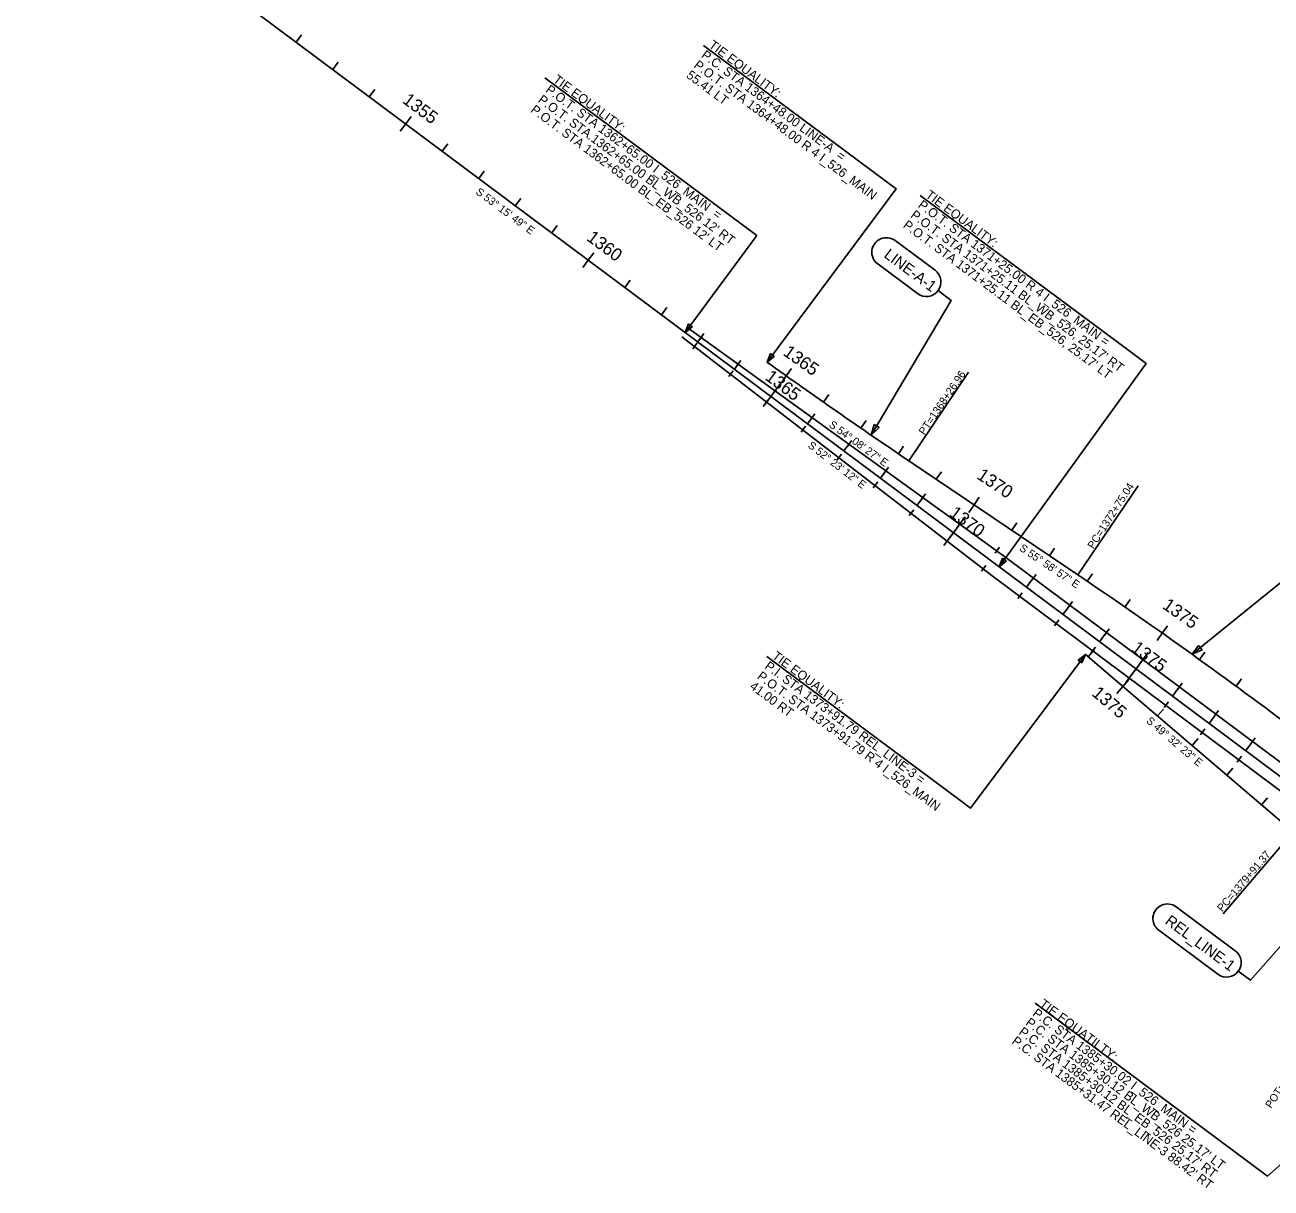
# Model space of a CAD drawing. Extents: x 2339300 to 2355400, y 360879 to 381052.
# Drawn here: x 2342035 to 2344770, y 370020 to 372573 of the extents above; entities that cross this region are included whole.
import ezdxf

# ---------------------------------------------------------------- set-up
doc = ezdxf.new("R2010")
doc.units = 0
for name, color, linetype in [('RD_HC_Cl', 7, 'Continuous'), ('RD_HC_CL_Rel', 7, 'Continuous'), ('RD_HC_Data', 7, 'Continuous'), ('RD_HC_Data_Rel', 7, 'Continuous'), ('RD_HC_Data_Tic', 7, 'Continuous'), ('RD_HC_Data_Tic_Rel', 7, 'Continuous'), ('RD_HC_TX_Rel_Sta50', 7, 'Continuous'), ('RD_HC_TX_Sta50', 7, 'Continuous'), ('RD_PD_Final_TX', 7, 'Continuous')]:
    doc.layers.add(name, color=color, linetype=linetype)

msp = doc.modelspace()

# ---------------------------------------------------------------- linework, layer by layer
at = {"layer": 'RD_HC_Cl'}
for p, q in [((2339299.7, 375020.3), (2345298.7, 370542.8)), ((2343974.3, 371616), (2344345.7, 371365.3))]:
    msp.add_line(p, q, dxfattribs=at)
for centre, radius, start, end in [((2351247.1, 382391.3), 13000, 234.31228, 235.98251), ((2338191.8, 362247.8), 11000, 52.99132, 55.9825)]:
    msp.add_arc(centre, radius, start, end, dxfattribs=at)
at = {"layer": 'RD_HC_CL_Rel'}
for p, q in [((2343490.7, 371907.2), (2344187.8, 371403.4)), ((2343476.4, 371888), (2344157.7, 371363.1)), ((2344187.8, 371403.4), (2345313.8, 370563)), ((2344157.7, 371363.1), (2345283.7, 370522.7)), ((2344362.1, 371190.8), (2344818.2, 370801.7))]:
    msp.add_line(p, q, dxfattribs=at)
at = {"layer": 'RD_HC_Data'}
for p, q in [((2344032.2, 372034), (2343944.5, 372099.3)), ((2343906.3, 372048), (2343994, 371982.7)), ((2343974.3, 371616), (2344105.5, 371810.3)), ((2344345.7, 371365.3), (2344477.9, 371561.2)), ((2344691.2, 370540.3), (2344561.4, 370636.8)), ((2344523.2, 370585.5), (2344653, 370488.9))]:
    msp.add_line(p, q, dxfattribs=at)
for points in [[(2344038.8, 371989.3), (2344067.9, 371967.6), (2343892, 371672.1)], [(2344888.7, 371354.8), (2344841.5, 371389.9), (2344596.3, 371191.1)], [(2344697.8, 370495.5), (2344724.3, 370475.8), (2344930.9, 370709.1)]]:
    msp.add_lwpolyline(points, dxfattribs=at)
for points in [[(2343898.5, 371695.2), (2343892, 371672.1), (2343909.2, 371688.8)], [(2344610.4, 371210.5), (2344596.3, 371191.1), (2344618.2, 371200.9)]]:
    msp.add_lwpolyline(points, close=True, dxfattribs=at)
for centre, start, end in [((2343925.4, 372073.6), 53.3467, 233.3467), ((2344013.1, 372008.4), 233.3467, 53.3467), ((2344542.3, 370611.1), 53.3467, 233.3467), ((2344672.1, 370514.6), 233.3467, 53.3467)]:
    msp.add_arc(centre, 32, start, end, dxfattribs=at)
at = {"layer": 'RD_HC_Data_Rel'}
msp.add_line((2344664.4, 370621.3), (2344818.2, 370801.7), dxfattribs=at)
at = {"layer": 'RD_HC_Data_Tic'}
for p, q in [((2342630.1, 372534.6), (2342642, 372550.7)), ((2342710.2, 372474.8), (2342722.2, 372490.9)), ((2342790.4, 372415), (2342802.3, 372431)), ((2342870.5, 372355.2), (2342882.5, 372371.2)), ((2342870.5, 372355.2), (2342858.5, 372339.2)), ((2342950.6, 372295.4), (2342962.6, 372311.4)), ((2343030.8, 372235.6), (2343042.7, 372251.6)), ((2343110.9, 372175.8), (2343122.9, 372191.8)), ((2343191.1, 372115.9), (2343203, 372132)), ((2343271.2, 372056.1), (2343283.2, 372072.2)), ((2343271.2, 372056.1), (2343259.2, 372040.1)), ((2343351.3, 371996.3), (2343363.3, 372012.3)), ((2343431.5, 371936.5), (2343443.4, 371952.5)), ((2343511.6, 371876.7), (2343523.6, 371892.7)), ((2343591.8, 371816.9), (2343603.7, 371832.9)), ((2343705.7, 371802.3), (2343694.1, 371786)), ((2343705.7, 371802.3), (2343717.3, 371818.6)), ((2343671.9, 371757.1), (2343683.9, 371773.1)), ((2343671.9, 371757.1), (2343659.9, 371741)), ((2343787.3, 371744.6), (2343798.8, 371761)), ((2343752, 371697.3), (2343764, 371713.3)), ((2343869.5, 371687.6), (2343880.8, 371704)), ((2343832.2, 371637.4), (2343844.1, 371653.5)), ((2343952, 371631.1), (2343963.2, 371647.7)), ((2343912.3, 371577.6), (2343924.3, 371593.7)), ((2344034.9, 371575.2), (2344046.1, 371591.7)), ((2343992.5, 371517.8), (2344004.4, 371533.8)), ((2344117.8, 371519.2), (2344129, 371535.8)), ((2344117.8, 371519.2), (2344106.6, 371502.6)), ((2344072.6, 371458), (2344084.6, 371474)), ((2344200.7, 371463.3), (2344211.8, 371479.8)), ((2344072.6, 371458), (2344060.6, 371442)), ((2344283.5, 371407.3), (2344294.7, 371423.9)), ((2344366.4, 371351.4), (2344377.6, 371367.9)), ((2344232.9, 371338.4), (2344244.8, 371354.4)), ((2344448.9, 371294.8), (2344460.3, 371311.3)), ((2344313, 371278.6), (2344325, 371294.6)), ((2344530.9, 371237.6), (2344542.4, 371253.9)), ((2344393.2, 371218.7), (2344405.1, 371234.8)), ((2344530.9, 371237.6), (2344519.4, 371221.2)), ((2344612.4, 371179.6), (2344624, 371195.8)), ((2344473.3, 371158.9), (2344485.3, 371175)), ((2344473.3, 371158.9), (2344461.3, 371142.9)), ((2344553.4, 371099.1), (2344565.4, 371115.2)), ((2344693.3, 371120.9), (2344705.1, 371137)), ((2344633.6, 371039.3), (2344645.5, 371055.3)), ((2344713.7, 370979.5), (2344725.7, 370995.5))]:
    msp.add_line(p, q, dxfattribs=at)
at = {"layer": 'RD_HC_Data_Tic_Rel'}
for p, q in [((2343515.6, 371881.9), (2343525, 371894.9)), ((2343500.5, 371861.9), (2343510.2, 371874.6)), ((2343596.6, 371823.3), (2343606, 371836.3)), ((2343579.7, 371800.9), (2343589.4, 371813.5)), ((2343674.2, 371759.9), (2343692.9, 371785.8)), ((2343655.2, 371735.1), (2343674.8, 371760.4)), ((2343758.7, 371706.1), (2343768.1, 371719.1)), ((2343738.1, 371678.8), (2343747.9, 371691.5)), ((2343839.8, 371647.6), (2343849.2, 371660.5)), ((2343817.3, 371617.8), (2343827.1, 371630.4)), ((2343920.8, 371589), (2343930.2, 371602)), ((2343896.5, 371556.7), (2343906.3, 371569.4)), ((2344001.9, 371530.4), (2344011.2, 371543.4)), ((2343975.7, 371495.7), (2343985.5, 371508.4)), ((2344079.4, 371467), (2344098.1, 371492.9)), ((2344051.3, 371429.9), (2344070.8, 371455.3)), ((2344164, 371413.2), (2344173.3, 371426.2)), ((2344134.2, 371373.6), (2344143.9, 371386.3)), ((2344244.3, 371353.8), (2344253.8, 371366.6)), ((2344214.2, 371313.5), (2344223.7, 371326.3)), ((2344324.4, 371294), (2344334, 371306.8)), ((2344294.3, 371253.6), (2344303.9, 371266.5)), ((2344404.5, 371234.2), (2344414.1, 371247)), ((2344368.3, 371185.5), (2344381.3, 371200.7)), ((2344374.4, 371193.8), (2344384, 371206.7)), ((2344481.1, 371169.6), (2344500.2, 371195.2)), ((2344451, 371129.2), (2344470.1, 371154.9)), ((2344444.4, 371120.6), (2344431.4, 371105.4)), ((2344444.4, 371120.6), (2344457.4, 371135.8)), ((2344564.8, 371114.5), (2344574.4, 371127.4)), ((2344534.7, 371074.2), (2344544.3, 371087)), ((2344520.5, 371055.7), (2344533.4, 371070.9)), ((2344645, 371054.7), (2344654.5, 371067.6)), ((2344596.6, 370990.8), (2344609.5, 371006)), ((2344614.8, 371014.4), (2344624.4, 371027.2)), ((2344725.1, 370994.9), (2344734.7, 371007.7)), ((2344695, 370954.6), (2344704.6, 370967.4)), ((2344672.6, 370925.9), (2344685.6, 370941.1)), ((2344748.7, 370861), (2344761.7, 370876.2))]:
    msp.add_line(p, q, dxfattribs=at)
at = {"layer": 'RD_PD_Final_TX'}
for p, q in [((2343927.4, 372227.2), (2343524, 372527.4)), ((2343641.1, 372110), (2343175.8, 372456.3)), ((2344451.5, 371862.2), (2343999.7, 372198.4)), ((2344089.1, 370869.2), (2343663.2, 371186.1)), ((2344721.9, 370075.7), (2344252, 370425.4))]:
    msp.add_line(p, q, dxfattribs=at)
for points in [[(2343927.4, 372227.2), (2343947, 372212.7), (2343663.4, 371832.6)], [(2343641.1, 372110), (2343483.6, 371897.6)], [(2344451.5, 371862.2), (2344495.4, 371829.6), (2344172.8, 371383.2)], [(2344089.1, 370869.2), (2344110.2, 370853.5), (2344362.1, 371190.8)], [(2344721.9, 370075.7), (2344761.8, 370046), (2345244.4, 370473.1)]]:
    msp.add_lwpolyline(points, dxfattribs=at)
for points in [[(2343490.9, 371916.2), (2343483.6, 371897.6), (2343499.2, 371910.1)], [(2343670.8, 371851.2), (2343663.4, 371832.6), (2343679.1, 371845)], [(2344179.9, 371401.9), (2344172.8, 371383.2), (2344188.3, 371395.9)], [(2344354.6, 371172.2), (2344362.1, 371190.8), (2344346.3, 371178.4)]]:
    msp.add_lwpolyline(points, close=True, dxfattribs=at)

# ---------------------------------------------------------------- texts
at = {"layer": 'RD_HC_Data'}
for s, height, rotation, p in [('S 53%%d 15\' 49" E', 17, 323.2637, (2343022.5, 372203)), ('LINE-A-1', 24, 323.3467, (2343918.2, 372064)), ('PT=1368+26.96', 17, 55.9825, (2344009, 371671)), ('PC=1372+75.04', 17, 57.1246, (2344379.8, 371421.1)), ('S 55%%d 58\' 57" E', 17, 325.9825, (2344215.7, 371420.5)), ('REL_LINE-1', 24, 323.3467, (2344535.2, 370601.5)), ('POT=100+00.00', 17, 56.3026, (2344769.7, 370193.2))]:
    msp.add_text(s, height=height, rotation=rotation, dxfattribs=at).set_placement(p)
at = {"layer": 'RD_HC_Data_Rel'}
for s, rotation, p in [('S 54%%d 08\' 27" E', 324.1408, (2343797.7, 371691.7)), ('S 52%%d 23\' 12" E', 322.3866, (2343751.5, 371646.8)), ('S 49%%d 32\' 23" E', 319.5396, (2344494.3, 371042.8)), ('PC=1379+91.37', 49.5396, (2344662.5, 370624.7))]:
    msp.add_text(s, height=17, rotation=rotation, dxfattribs=at).set_placement(p)
at = {"layer": 'RD_HC_TX_Rel_Sta50'}
msp.add_text('1375', height=28, rotation=319.5396, dxfattribs=at).set_placement((2344374.4, 371102.4))
at = {"layer": 'RD_HC_TX_Sta50'}
for s, rotation, p in [('1355', 323.2637, (2342861.2, 372403.2)), ('1360', 323.2637, (2343265.6, 372101.4)), ('1365', 324.5415, (2343696.7, 371849.3)), ('1365', 323.2637, (2343657.1, 371795.5)), ('1370', 325.9825, (2344121.8, 371578.4)), ('1370', 323.2637, (2344061.5, 371496.5)), ('1375', 324.8108, (2344529.2, 371293.6)), ('1375', 323.2637, (2344460.8, 371200.2))]:
    msp.add_text(s, height=28, rotation=rotation, dxfattribs=at).set_placement(p)
at = {"layer": 'RD_PD_Final_TX'}
for s, p in [('TIE EQUALITY:', (2343533.9, 372524.7)), ('P.C. STA 1364+48.00 LINE-A  =', (2343517.5, 372502.6)), ('P.O.T. STA 1364+48.00 R 4 I_526_MAIN', (2343501.1, 372480.6)), ('TIE EQUALITY:', (2343192.1, 372448.8)), ('55.41 LT', (2343484.7, 372458.5)), ('P.O.T. STA 1362+65.00 I_526_MAIN  =', (2343175.6, 372426.7)), ("P.O.T. STA.1362+65.00 BL_WB_526 12' RT", (2343159.2, 372404.7)), ("P.O.T. STA 1362+65.00 BL_EB_526 12' LT", (2343142.8, 372382.6)), ('TIE EQUALITY:', (2344009.6, 372195.7)), ('P.O.T. STA 1371+25.00 R 4 I_526_MAIN =', (2343993.2, 372173.7)), ("P.O.T. STA 1371+25.11 BL_WB_526, 25.17' RT", (2343976.8, 372151.6)), ("P.O.T. STA 1371+25.11 BL_EB_526, 25.17' LT", (2343960.4, 372129.5)), ('TIE EQUALITY:', (2343673.1, 371183.5)), ('P.I. STA 1373+91.79 REL_LINE-3 =', (2343656.6, 371161.4)), ('P.O.T. STA 1373+91.79 R 4 I_526_MAIN', (2343640.2, 371139.3)), ('41.00 RT', (2343623.8, 371117.3)), ('TIE EQUATILTY:', (2344259.6, 370419.7)), ('P.C. STA 1385+30.02 I_526_MAIN =', (2344244.5, 370399.4)), ("P.C. STA 1385+30.12 BL_WB_526 25.17' LT", (2344229.3, 370379.1)), ("P.C. STA 1385+31.47 REL_LINE-3 88.42' RT", (2344199, 370338.4)), ("P.C. STA 1385+30.12 BL_EB_526 25.17' RT", (2344214.2, 370358.7))]:
    msp.add_text(s, height=20, rotation=323.3467, dxfattribs=at).set_placement(p)

doc.saveas('drawing.dxf')
